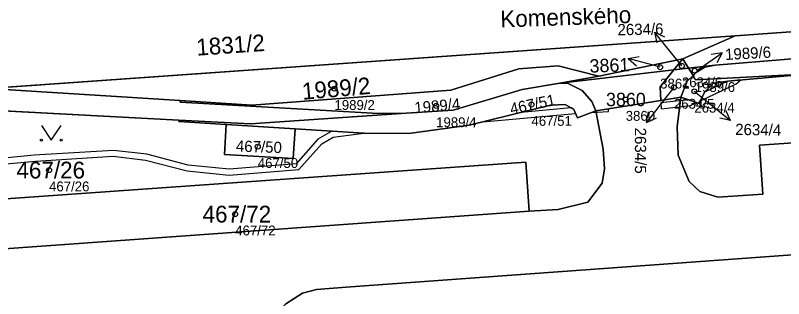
# Model space of a CAD drawing. Extents: x -653098 to -649479, y -997642 to -992666.
# Drawn here: x -651361.8 to -651284, y -995296.6 to -995268 of the extents above; entities that cross this region are included whole.
import ezdxf

# ---------------------------------------------------------------- set-up
doc = ezdxf.new("R2010")
doc.units = 0
for name, color, linetype in [('Definiční body', 7, 'Continuous'), ('Hranice parcel', 7, 'Continuous'), ('Parcelní čísla', 7, 'Continuous'), ('Polygon parcely', 7, 'Continuous'), ('Pop  PČ popisy', 7, 'Continuous'), ('Věcná břemena k části', 7, 'Continuous'), ('Značky kultur', 7, 'Continuous')]:
    doc.layers.add(name, color=color, linetype=linetype)

msp = doc.modelspace()

# ---------------------------------------------------------------- linework, layer by layer
at = {"layer": 'Definiční body'}
for centre in [(-651294.28, -995273.08), (-651296.48, -995273.21), (-651292.98, -995273.56), (-651329.48, -995275.38), (-651295.09, -995275.26), (-651293.02, -995275.65), (-651309.52, -995276.99), (-651299.97, -995276.48), (-651319.18, -995277.13), (-651337.25, -995281.26), (-651358.4, -995283.63), (-651339.54, -995288.09)]:
    msp.add_circle(centre, 0.25, dxfattribs=at)
at = {"layer": 'Hranice parcel'}
for p, q in [((-651288.88, -995270.03), (-651364.52, -995275.37)), ((-651294.2, -995272.35), (-651288.88, -995270.03)), ((-651302.71, -995274.1), (-651294.2, -995272.35)), ((-651294.2, -995272.35), (-651295.11, -995273.49)), ((-651294.2, -995272.35), (-651293.6, -995273.32)), ((-651293.6, -995273.32), (-651295.11, -995273.49)), ((-651293.6, -995273.32), (-651290.91, -995273.01)), ((-651293.6, -995273.32), (-651293.15, -995274.05)), ((-651306.65, -995274.82), (-651302.71, -995274.1)), ((-651345.11, -995276.59), (-651364.52, -995275.37)), ((-651296.42, -995276.57), (-651294.38, -995276.24)), ((-651345.26, -995278.56), (-651363.73, -995277.6)), ((-651333.48, -995279.45), (-651340.46, -995279.02)), ((-651309.74, -995287.8), (-651364.83, -995291.75))]:
    msp.add_line(p, q, dxfattribs=at)
for points in [[(-651222.99, -995265.41), (-651227.7, -995265.81), (-651232.31, -995266.25), (-651237.27, -995266.87), (-651257.46, -995269.72), (-651260.89, -995270.24), (-651263.22, -995270.59), (-651267.87, -995271.12), (-651290.91, -995273.01)], [(-651222.99, -995265.41), (-651278.07, -995269.27), (-651288.88, -995270.03)], [(-651345.11, -995276.59), (-651337.85, -995277.05), (-651317.7, -995275.53), (-651310.8, -995273.37), (-651306.81, -995273.06), (-651302.71, -995274.1)], [(-651295.11, -995273.49), (-651302.55, -995274.35), (-651306.65, -995274.82)], [(-651295.11, -995273.49), (-651296.48, -995275.2), (-651296.42, -995276.57)], [(-651290.91, -995273.01), (-651291.97, -995273.19), (-651292.9, -995273.79), (-651293.15, -995274.05)], [(-651281.33, -995273.88), (-651289.62, -995274.61), (-651291.07, -995274.82), (-651291.98, -995275.74), (-651292.53, -995276.89), (-651293.47, -995276.56), (-651294.38, -995276.24)], [(-651293.15, -995274.05), (-651293.73, -995274.64), (-651294.38, -995276.24)], [(-651293.15, -995274.05), (-651292.89, -995274.48), (-651281.33, -995273.88)], [(-651306.65, -995274.82), (-651310.46, -995275.47), (-651317.44, -995277.56), (-651322.23, -995277.88)], [(-651303, -995277.63), (-651303.41, -995276.69), (-651304.4, -995275.56), (-651305.88, -995274.84), (-651306.65, -995274.82)], [(-651322.23, -995277.88), (-651325.02, -995277.91), (-651345.12, -995276.74), (-651345.11, -995276.59)], [(-651296.42, -995276.57), (-651301.72, -995277.42), (-651303, -995277.63)], [(-651294.38, -995276.24), (-651294.75, -995279.24), (-651294.65, -995282.11), (-651293.54, -995284.8), (-651292.46, -995285.81), (-651290.62, -995286.38), (-651286.08, -995286.07), (-651286.42, -995281.1), (-651271.16, -995280.05), (-651270.83, -995285.01), (-651243, -995282.98), (-651242.49, -995282.97), (-651241.48, -995283.14), (-651240.53, -995283.39), (-651238.15, -995284.24), (-651235.54, -995285.49), (-651232.95, -995287.04), (-651232.12, -995287.63), (-651231.43, -995288.42), (-651231.1, -995289.37), (-651230.61, -995295.84), (-651225.65, -995295.46), (-651223.3, -995327.45)], [(-651303, -995277.63), (-651304.85, -995278.35), (-651305.24, -995277.48), (-651306.12, -995276.99), (-651307.6, -995277.05), (-651315.83, -995279.08), (-651321.96, -995279.91), (-651326.52, -995279.88), (-651333.48, -995279.45)], [(-651345.26, -995278.56), (-651338, -995278.94), (-651322.23, -995277.88)], [(-651309.74, -995287.8), (-651306.8, -995287.61), (-651303.81, -995286.89), (-651302.35, -995284.94), (-651302.11, -995283.5), (-651302.25, -995281.5), (-651303, -995277.63)], [(-651340.46, -995279.02), (-651345.26, -995278.72), (-651345.26, -995278.56)], [(-651333.48, -995279.45), (-651333.65, -995282.44), (-651340.64, -995282.04), (-651340.46, -995279.02)], [(-651364.83, -995291.75), (-651365.2, -995286.72), (-651310.08, -995282.82), (-651309.74, -995287.8)], [(-651332.72, -995296.1), (-651331.29, -995295.71), (-651328.3, -995295.48), (-651243.44, -995289.33)], [(-651267.93, -995320.09), (-651306.07, -995322.86), (-651306.43, -995317.91), (-651314.35, -995318.49), (-651313.99, -995323.44), (-651328.95, -995324.51), (-651328.57, -995329.48), (-651329.55, -995329.55), (-651330.53, -995329.39), (-651331.46, -995329.05), (-651333.09, -995327.92), (-651334.29, -995326.31), (-651334.67, -995325.39), (-651334.86, -995324.41), (-651336.39, -995303.78), (-651336.44, -995301.29), (-651336.05, -995299.35), (-651335.44, -995298.25), (-651334.42, -995297.16), (-651332.72, -995296.1)]]:
    msp.add_lwpolyline(points, dxfattribs=at)
at = {"layer": 'Polygon parcely'}
for points in [[(-651423.27, -995280.83), (-651401.44, -995278.16), (-651364.52, -995275.37), (-651288.88, -995270.03), (-651278.07, -995269.27), (-651222.99, -995265.41), (-651173.69, -995261.95), (-651166.07, -995261.41), (-651149.15, -995260.24), (-651121.46, -995258.29), (-651108.69, -995257.36)], [(-651173.69, -995261.95), (-651222.99, -995265.41), (-651227.7, -995265.81), (-651232.31, -995266.25), (-651237.27, -995266.87), (-651257.46, -995269.72), (-651260.89, -995270.24), (-651263.22, -995270.59), (-651267.87, -995271.12), (-651290.91, -995273.01), (-651291.97, -995273.19), (-651292.9, -995273.79), (-651293.15, -995274.05), (-651292.89, -995274.48), (-651281.33, -995273.88), (-651268.58, -995273.22), (-651235.31, -995271.48), (-651223.77, -995271.11), (-651219.62, -995270.98)], [(-651281.33, -995273.88), (-651289.62, -995274.61), (-651291.07, -995274.82), (-651291.98, -995275.74), (-651292.53, -995276.89), (-651293.47, -995276.56), (-651294.38, -995276.24), (-651294.75, -995279.24), (-651294.65, -995282.11), (-651293.54, -995284.8), (-651292.46, -995285.81), (-651290.62, -995286.38), (-651286.08, -995286.07), (-651286.42, -995281.1), (-651271.16, -995280.05)], [(-651271.16, -995280.05), (-651286.42, -995281.1), (-651286.08, -995286.07), (-651290.62, -995286.38), (-651292.46, -995285.81), (-651293.54, -995284.8), (-651294.65, -995282.11), (-651294.75, -995279.24), (-651294.38, -995276.24), (-651296.42, -995276.57), (-651301.72, -995277.42), (-651303, -995277.63), (-651302.25, -995281.5), (-651302.11, -995283.5), (-651302.35, -995284.94), (-651303.81, -995286.89), (-651306.8, -995287.61), (-651309.74, -995287.8), (-651364.83, -995291.75)], [(-651365.2, -995286.72), (-651310.08, -995282.82), (-651309.74, -995287.8), (-651306.8, -995287.61), (-651303.81, -995286.89), (-651302.35, -995284.94), (-651302.11, -995283.5), (-651302.25, -995281.5), (-651303, -995277.63), (-651304.85, -995278.35), (-651305.24, -995277.48), (-651306.12, -995276.99), (-651307.6, -995277.05), (-651315.83, -995279.08), (-651321.96, -995279.91), (-651326.52, -995279.88), (-651333.48, -995279.45), (-651333.65, -995282.44), (-651340.64, -995282.04), (-651340.46, -995279.02), (-651345.26, -995278.72), (-651345.26, -995278.56), (-651363.73, -995277.6)], [(-651243.44, -995289.33), (-651328.3, -995295.48), (-651331.29, -995295.71), (-651332.72, -995296.1), (-651334.42, -995297.16), (-651335.44, -995298.25), (-651336.05, -995299.35), (-651336.44, -995301.29), (-651336.39, -995303.78), (-651334.86, -995324.41), (-651334.67, -995325.39), (-651334.29, -995326.31), (-651333.09, -995327.92), (-651331.46, -995329.05), (-651330.53, -995329.39), (-651329.55, -995329.55), (-651328.57, -995329.48), (-651328.95, -995324.51), (-651313.99, -995323.44), (-651314.35, -995318.49), (-651306.43, -995317.91), (-651306.07, -995322.86), (-651267.93, -995320.09)], [(-651267.93, -995320.09), (-651306.07, -995322.86), (-651306.43, -995317.91), (-651314.35, -995318.49), (-651313.99, -995323.44), (-651328.95, -995324.51), (-651328.57, -995329.48), (-651329.55, -995329.55), (-651330.53, -995329.39), (-651331.46, -995329.05), (-651333.09, -995327.92), (-651334.29, -995326.31), (-651334.67, -995325.39), (-651334.86, -995324.41), (-651336.39, -995303.78), (-651336.44, -995301.29), (-651336.05, -995299.35), (-651335.44, -995298.25), (-651334.42, -995297.16), (-651332.72, -995296.1), (-651331.29, -995295.71), (-651328.3, -995295.48), (-651243.44, -995289.33)]]:
    msp.add_lwpolyline(points, dxfattribs=at)
for points in [[(-651294.2, -995272.35), (-651293.6, -995273.32), (-651290.91, -995273.01), (-651267.87, -995271.12), (-651263.22, -995270.59), (-651260.89, -995270.24), (-651257.46, -995269.72), (-651237.27, -995266.87), (-651232.31, -995266.25), (-651227.7, -995265.81), (-651222.99, -995265.41), (-651278.07, -995269.27), (-651288.88, -995270.03)], [(-651288.88, -995270.03), (-651364.52, -995275.37), (-651345.11, -995276.59), (-651337.85, -995277.05), (-651317.7, -995275.53), (-651310.8, -995273.37), (-651306.81, -995273.06), (-651302.71, -995274.1), (-651294.2, -995272.35)], [(-651302.71, -995274.1), (-651306.65, -995274.82), (-651302.55, -995274.35), (-651295.11, -995273.49), (-651294.2, -995272.35)], [(-651295.11, -995273.49), (-651293.6, -995273.32), (-651294.2, -995272.35)], [(-651302.71, -995274.1), (-651306.81, -995273.06), (-651310.8, -995273.37), (-651317.7, -995275.53), (-651337.85, -995277.05), (-651345.11, -995276.59), (-651345.12, -995276.74), (-651325.02, -995277.91), (-651322.23, -995277.88), (-651317.44, -995277.56), (-651310.46, -995275.47), (-651306.65, -995274.82)], [(-651296.42, -995276.57), (-651296.48, -995275.2), (-651295.11, -995273.49), (-651302.55, -995274.35), (-651306.65, -995274.82), (-651305.88, -995274.84), (-651304.4, -995275.56), (-651303.41, -995276.69), (-651303, -995277.63), (-651301.72, -995277.42)], [(-651296.48, -995275.2), (-651296.42, -995276.57), (-651294.38, -995276.24), (-651293.73, -995274.64), (-651293.15, -995274.05), (-651293.6, -995273.32), (-651295.11, -995273.49)], [(-651293.6, -995273.32), (-651293.15, -995274.05), (-651292.9, -995273.79), (-651291.97, -995273.19), (-651290.91, -995273.01)], [(-651294.38, -995276.24), (-651293.47, -995276.56), (-651292.53, -995276.89), (-651291.98, -995275.74), (-651291.07, -995274.82), (-651289.62, -995274.61), (-651281.33, -995273.88), (-651292.89, -995274.48), (-651293.15, -995274.05), (-651293.73, -995274.64)], [(-651303, -995277.63), (-651303.41, -995276.69), (-651304.4, -995275.56), (-651305.88, -995274.84), (-651306.65, -995274.82), (-651310.46, -995275.47), (-651317.44, -995277.56), (-651322.23, -995277.88), (-651338, -995278.94), (-651345.26, -995278.56), (-651345.26, -995278.72), (-651340.46, -995279.02), (-651333.48, -995279.45), (-651326.52, -995279.88), (-651321.96, -995279.91), (-651315.83, -995279.08), (-651307.6, -995277.05), (-651306.12, -995276.99), (-651305.24, -995277.48), (-651304.85, -995278.35)], [(-651363.73, -995277.6), (-651345.26, -995278.56), (-651338, -995278.94), (-651322.23, -995277.88), (-651325.02, -995277.91), (-651345.12, -995276.74), (-651345.11, -995276.59), (-651364.52, -995275.37), (-651401.44, -995278.16), (-651423.27, -995280.83), (-651435.76, -995285.16), (-651440.09, -995288.54), (-651454.39, -995308.37), (-651441.59, -995292.96), (-651434.65, -995287.1), (-651422.77, -995282.8), (-651419.93, -995282.46), (-651400.99, -995280.21), (-651381.88, -995279.09), (-651380.16, -995279), (-651375.2, -995278.56), (-651372.11, -995278.29), (-651364.11, -995277.58)], [(-651340.46, -995279.02), (-651340.64, -995282.04), (-651333.65, -995282.44), (-651333.48, -995279.45)], [(-651309.74, -995287.8), (-651310.08, -995282.82), (-651365.2, -995286.72), (-651364.83, -995291.75)]]:
    msp.add_lwpolyline(points, close=True, dxfattribs=at)
at = {"layer": 'Pop  PČ popisy'}
for p, q in [((-651295.17, -995271.99), (-651297.059, -995269.658)), ((-651297.059, -995269.658), (-651296.039, -995270.121)), ((-651297.059, -995269.658), (-651296.817, -995270.751)), ((-651294.28, -995273.08), (-651295.17, -995271.99)), ((-651292.65, -995273.49), (-651290.192, -995271.769)), ((-651290.192, -995271.769), (-651291.299, -995271.933)), ((-651290.192, -995271.769), (-651290.725, -995272.753)), ((-651299.719, -995272.343), (-651298.622, -995272.119)), ((-651296.82, -995273.12), (-651299.719, -995272.343)), ((-651299.719, -995272.343), (-651298.881, -995273.086)), ((-651296.48, -995273.21), (-651296.82, -995273.12)), ((-651292.67, -995273.5), (-651292.65, -995273.49)), ((-651295.09, -995275.26), (-651296.03, -995276.45)), ((-651293.02, -995275.65), (-651291.69, -995276.73)), ((-651296.03, -995276.45), (-651297.878, -995278.815)), ((-651291.69, -995276.73), (-651289.358, -995278.619)), ((-651297.878, -995278.815), (-651297.656, -995277.717)), ((-651289.358, -995278.619), (-651289.821, -995277.599)), ((-651297.878, -995278.815), (-651296.866, -995278.334)), ((-651289.358, -995278.619), (-651290.451, -995278.377))]:
    msp.add_line(p, q, dxfattribs=at)
at = {"layer": 'Věcná břemena k části'}
for points in [[(-651292.39, -995276.6), (-651288.79, -995274.9), (-651288.31, -995274.49), (-651289.62, -995274.61), (-651291.98, -995275.74)], [(-651296.39, -995277.42), (-651293.4, -995277.08), (-651292.8, -995276.8), (-651293.61, -995276.52), (-651296.41, -995276.81)], [(-651310.59, -995277.79), (-651314.44, -995278.74), (-651305.06, -995277.89), (-651305.24, -995277.48), (-651305.51, -995277.33)], [(-651303.39, -995277.78), (-651301.72, -995277.7), (-651301.72, -995277.42), (-651303, -995277.63)]]:
    msp.add_lwpolyline(points, close=True, dxfattribs=at)
msp.add_lwpolyline([(-651367.63, -995283.43), (-651359.78, -995282.71), (-651351.89, -995282.23), (-651348.62, -995282.61), (-651344.41, -995283.72), (-651340.16, -995284.16), (-651333.08, -995283.56), (-651330.76, -995280.97), (-651329.61, -995280.29), (-651326.52, -995279.88), (-651329.75, -995279.68), (-651331.15, -995280.5), (-651333.37, -995282.98), (-651340.16, -995283.55), (-651344.3, -995283.13), (-651348.5, -995282.02), (-651351.88, -995281.63), (-651359.9, -995282.12), (-651369.5, -995283.07)], dxfattribs=at)
at = {"layer": 'Značky kultur'}
msp.add_lwpolyline([(-651359.18, -995279.099), (-651358.18, -995280.6), (-651357.18, -995279.099)], dxfattribs=at)
for centre in [(-651359.18, -995280.599), (-651357.18, -995280.599)]:
    msp.add_circle(centre, 0.1, dxfattribs=at)

# ---------------------------------------------------------------- texts
at = {"layer": 'Definiční body'}
for s, p in [('3861', (-651296.48, -995275.366)), ('2634/6', (-651294.28, -995275.236)), ('1989/6', (-651292.98, -995275.716)), ('1989/2', (-651329.48, -995277.536)), ('2634/5', (-651295.09, -995277.416)), ('2634/4', (-651293.02, -995277.806)), ('1989/4', (-651319.18, -995279.286)), ('467/51', (-651309.52, -995279.146)), ('3860', (-651299.97, -995278.636)), ('467/50', (-651337.25, -995283.416)), ('467/26', (-651358.4, -995285.786)), ('467/72', (-651339.54, -995290.246))]:
    msp.add_text(s, height=1, dxfattribs=at).set_placement(p)
at = {"layer": 'Parcelní čísla'}
for s, height, rotation, p in [('2634/6', 1.139, 1, (-651300.794, -995269.978)), ('1831/2', 1.7, 4, (-651343.42, -995272.047)), ('1989/6', 1.139, 3, (-651289.872, -995272.484)), ('3861', 1.353, 2, (-651303.61, -995273.765)), ('1989/2', 1.7, 5, (-651332.699, -995276.514)), ('1989/4', 1.139, 5, (-651321.336, -995277.89)), ('467/51', 1.139, 12, (-651311.568, -995278.007)), ('2634/4', 1.139, 359, (-651288.884, -995280.07)), ('2634/5', 1.139, 270, (-651299.039, -995279.335)), ('467/50', 1.139, 358, (-651339.483, -995281.751))]:
    msp.add_text(s, height=height, rotation=rotation, dxfattribs=at).set_placement(p)
for s, height, p in [('3860', 1.353, (-651301.965, -995277.156)), ('467/26', 1.7, (-651361.705, -995284.48)), ('467/72', 1.7, (-651342.845, -995288.94))]:
    msp.add_text(s, height=height, dxfattribs=at).set_placement(p)
at = {"layer": 'Pop  PČ popisy'}
msp.add_text('Komenského', height=1.7, rotation=2, dxfattribs=at).set_placement((-651312.65, -995269.189))

doc.saveas('drawing.dxf')
